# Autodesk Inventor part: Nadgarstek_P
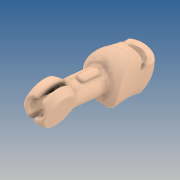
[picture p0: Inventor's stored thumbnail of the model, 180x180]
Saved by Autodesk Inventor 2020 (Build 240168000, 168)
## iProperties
Created: 2019-10
Part Number: Nadgarstek_P
Material: GFRP
Document SubType Name: Modeling
Designer: yello
Density: 1.75 g/cm^3
Appearance: Default
Author: yello
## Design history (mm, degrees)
feature "Body1"
body "Solid1"
